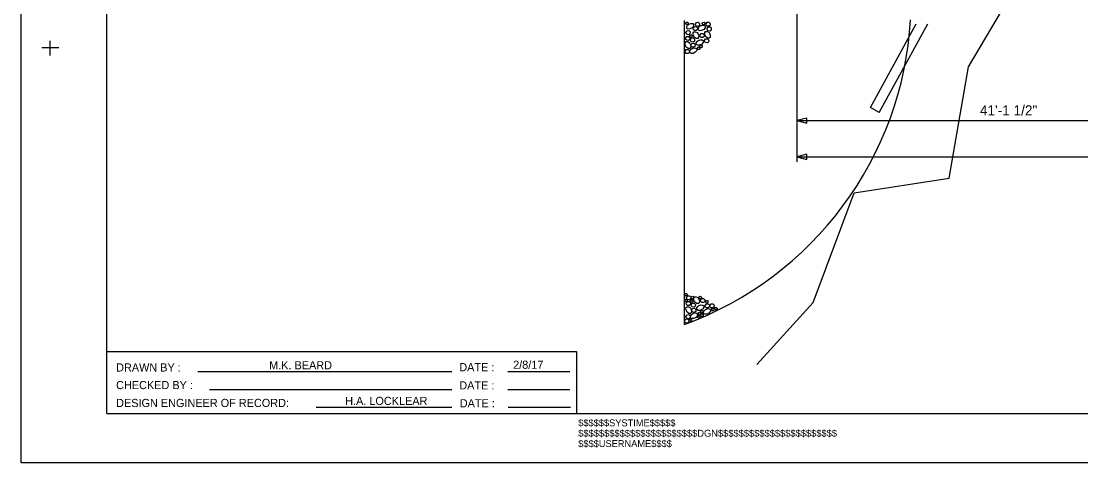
# Model space of a CAD drawing. Extents: x 985 to 1514, y -701 to -21.
# Drawn here: x 998.7 to 1102.9, y -220.9 to -177.5 of the extents above; entities that cross this region are included whole.
import ezdxf

# ---------------------------------------------------------------- set-up
doc = ezdxf.new("R2010")
doc.units = 0
for name, color, linetype in [('Auto Dimensioning', 7, 'Continuous'), ('Exist Hydro Stream or Body of Water', 7, 'Continuous'), ('Exist Structure Major Bridge Seam', 7, 'Continuous'), ('Miscellaneous Lines CELL', 7, 'Continuous'), ('Plan Sheet CELL', 7, 'Continuous'), ('Plot Label CELL', 7, 'Continuous'), ('Plot Shape CELL', 7, 'Continuous'), ('Sub End Bent Cap Lines CELL', 7, 'Continuous'), ('Subtitle Text', 7, 'Continuous'), ('Sup Concrete Girder Lines', 7, 'Continuous'), ('Text', 7, 'Continuous')]:
    doc.layers.add(name, color=color, linetype=linetype)

# ---------------------------------------------------------------- blocks, each defined once
blk = doc.blocks.new('AH')
at = {"layer": 'Sub End Bent Cap Lines CELL'}
blk.add_lwpolyline([(0, 0), (-1.25, 0.31), (-1.25, -0.31)], close=True, dxfattribs=at)

msp = doc.modelspace()

# ---------------------------------------------------------------- linework, layer by layer
at = {"layer": 'Auto Dimensioning'}
for p, q in [((1075, -159.49), (1075, -191.32)), ((1075, -187.25), (1116.12, -187.25)), ((1075, -190.82), (1157.23, -190.82))]:
    msp.add_line(p, q, dxfattribs=at)
at = {"layer": 'Exist Hydro Stream or Body of Water'}
for points in [[(1091.88, -181.98), (1095.35, -176.15), (1089.85, -166.68)], [(1071.09, -211.26), (1076.62, -205.16), (1080.66, -194.36), (1089.98, -192.93), (1091.88, -181.98)]]:
    msp.add_lwpolyline(points, dxfattribs=at)
at = {"layer": 'Exist Structure Major Bridge Seam'}
for p, q in [((1082.24, -185.97), (1086.76, -177.73)), ((1083.12, -186.45), (1087.9, -177.73)), ((1083.12, -186.45), (1082.24, -185.97))]:
    msp.add_line(p, q, dxfattribs=at)
at = {"layer": 'Miscellaneous Lines CELL'}
for points in [[(1064.08, -177.66), (1064.14, -177.56), (1064.25, -177.56), (1064.33, -177.63), (1064.32, -177.74), (1064.25, -177.8), (1064.14, -177.79), (1064.09, -177.74), (1064.08, -177.66)], [(1064.37, -177.78), (1064.58, -177.7), (1064.77, -177.71), (1064.86, -177.8), (1064.86, -177.96), (1064.72, -178.14), (1064.5, -178.24), (1064.3, -178.25), (1064.19, -178.17), (1064.18, -178), (1064.27, -177.86), (1064.38, -177.78)], [(1064.82, -178.18), (1064.93, -178.02), (1065.11, -178.01), (1065.24, -178.14), (1065.22, -178.32), (1065.11, -178.41), (1064.93, -178.4), (1064.85, -178.32), (1064.82, -178.18)], [(1065.03, -177.76), (1065.14, -177.6), (1065.32, -177.59), (1065.45, -177.72), (1065.43, -177.9), (1065.32, -177.99), (1065.14, -177.98), (1065.06, -177.9), (1065.03, -177.76)], [(1065.51, -177.95), (1065.72, -177.87), (1065.91, -177.88), (1066, -177.97), (1066, -178.13), (1065.86, -178.3), (1065.64, -178.41), (1065.44, -178.42), (1065.33, -178.33), (1065.32, -178.17), (1065.41, -178.03), (1065.51, -177.95)], [(1065.71, -177.7), (1065.78, -177.6), (1065.89, -177.59), (1065.96, -177.67), (1065.95, -177.78), (1065.88, -177.83), (1065.78, -177.83), (1065.73, -177.78), (1065.71, -177.7)], [(1066.08, -177.74), (1066.19, -177.58), (1066.37, -177.57), (1066.49, -177.7), (1066.48, -177.88), (1066.36, -177.97), (1066.19, -177.96), (1066.1, -177.88), (1066.08, -177.74)], [(1066.18, -178.21), (1066.3, -178.05), (1066.47, -178.04), (1066.6, -178.17), (1066.58, -178.35), (1066.47, -178.45), (1066.29, -178.43), (1066.21, -178.35), (1066.18, -178.21)], [(1064.07, -179.14), (1064.18, -178.98), (1064.36, -178.97), (1064.49, -179.1), (1064.47, -179.28), (1064.36, -179.37), (1064.18, -179.35), (1064.1, -179.27), (1064.07, -179.14)], [(1064.1, -178.58), (1064.21, -178.42), (1064.39, -178.41), (1064.52, -178.54), (1064.5, -178.72), (1064.39, -178.81), (1064.21, -178.8), (1064.13, -178.72), (1064.1, -178.58)], [(1064.49, -178.91), (1064.55, -178.81), (1064.66, -178.81), (1064.74, -178.88), (1064.72, -178.99), (1064.66, -179.05), (1064.55, -179.04), (1064.5, -178.99), (1064.49, -178.91)], [(1064.54, -179.29), (1064.66, -179.13), (1064.83, -179.12), (1064.96, -179.25), (1064.94, -179.43), (1064.83, -179.53), (1064.65, -179.51), (1064.57, -179.43), (1064.54, -179.29)], [(1065.28, -178.69), (1065.36, -178.9), (1065.34, -179.1), (1065.26, -179.19), (1065.1, -179.19), (1064.92, -179.05), (1064.82, -178.83), (1064.81, -178.63), (1064.89, -178.52), (1065.05, -178.51), (1065.2, -178.6), (1065.28, -178.7)], [(1065.48, -178.85), (1065.59, -178.69), (1065.77, -178.68), (1065.89, -178.81), (1065.88, -178.99), (1065.77, -179.09), (1065.59, -179.07), (1065.51, -178.99), (1065.48, -178.85)], [(1065.93, -179.37), (1066.04, -179.21), (1066.22, -179.2), (1066.34, -179.33), (1066.32, -179.51), (1066.21, -179.6), (1066.04, -179.59), (1065.95, -179.51), (1065.93, -179.37)], [(1066.42, -178.67), (1066.5, -178.88), (1066.48, -179.07), (1066.4, -179.16), (1066.24, -179.16), (1066.06, -179.02), (1065.95, -178.8), (1065.95, -178.6), (1066.03, -178.49), (1066.19, -178.48), (1066.34, -178.57), (1066.42, -178.68)], [(1064.5, -179.67), (1064.58, -179.88), (1064.56, -180.07), (1064.48, -180.16), (1064.32, -180.16), (1064.14, -180.02), (1064.04, -179.81), (1064.03, -179.61), (1064.11, -179.49), (1064.28, -179.48), (1064.42, -179.57), (1064.5, -179.68)], [(1064.03, -180.43), (1064.14, -180.28), (1064.32, -180.27), (1064.44, -180.39), (1064.42, -180.57), (1064.31, -180.67), (1064.14, -180.65), (1064.05, -180.57), (1064.03, -180.43)], [(1064.67, -180.19), (1064.88, -180.11), (1065.07, -180.12), (1065.17, -180.21), (1065.16, -180.37), (1065.02, -180.54), (1064.81, -180.65), (1064.61, -180.65), (1064.49, -180.57), (1064.48, -180.41), (1064.57, -180.27), (1064.68, -180.18)], [(1064.59, -179.82), (1064.71, -179.66), (1064.88, -179.65), (1065.01, -179.78), (1064.99, -179.96), (1064.88, -180.05), (1064.7, -180.04), (1064.62, -179.96), (1064.59, -179.82)], [(1065.3, -179.39), (1065.51, -179.3), (1065.7, -179.32), (1065.8, -179.41), (1065.79, -179.56), (1065.65, -179.74), (1065.44, -179.85), (1065.24, -179.85), (1065.12, -179.77), (1065.11, -179.61), (1065.21, -179.47), (1065.31, -179.38)], [(1065.22, -180.14), (1065.29, -180.05), (1065.4, -180.04), (1065.47, -180.12), (1065.46, -180.23), (1065.39, -180.28), (1065.29, -180.28), (1065.24, -180.23), (1065.22, -180.14)], [(1065.45, -179.95), (1065.52, -179.85), (1065.63, -179.85), (1065.7, -179.92), (1065.69, -180.03), (1065.63, -180.09), (1065.52, -180.08), (1065.47, -180.03), (1065.45, -179.95)], [(1063.98, -204.36), (1064.05, -204.26), (1064.15, -204.26), (1064.23, -204.33), (1064.22, -204.44), (1064.15, -204.5), (1064.05, -204.49), (1064, -204.44), (1063.98, -204.36)], [(1063.98, -204.92), (1064.05, -204.83), (1064.15, -204.82), (1064.23, -204.9), (1064.22, -205.01), (1064.15, -205.06), (1064.05, -205.05), (1064, -205.01), (1063.98, -204.92)], [(1064.14, -205.21), (1064.25, -205.05), (1064.43, -205.04), (1064.56, -205.17), (1064.54, -205.35), (1064.43, -205.44), (1064.25, -205.43), (1064.17, -205.35), (1064.14, -205.21)], [(1064.17, -204.66), (1064.28, -204.5), (1064.46, -204.49), (1064.59, -204.62), (1064.57, -204.8), (1064.46, -204.89), (1064.28, -204.88), (1064.2, -204.8), (1064.17, -204.66)], [(1064.56, -204.98), (1064.62, -204.89), (1064.73, -204.88), (1064.81, -204.96), (1064.79, -205.07), (1064.73, -205.12), (1064.62, -205.11), (1064.57, -205.07), (1064.56, -204.98)], [(1064.61, -204.64), (1064.68, -204.55), (1064.79, -204.54), (1064.86, -204.62), (1064.85, -204.73), (1064.79, -204.78), (1064.68, -204.78), (1064.63, -204.73), (1064.61, -204.64)], [(1064.61, -205.37), (1064.73, -205.21), (1064.9, -205.2), (1065.03, -205.33), (1065.01, -205.51), (1064.9, -205.6), (1064.72, -205.59), (1064.64, -205.51), (1064.61, -205.37)], [(1065.35, -204.77), (1065.43, -204.98), (1065.41, -205.17), (1065.33, -205.26), (1065.17, -205.26), (1064.99, -205.12), (1064.89, -204.91), (1064.88, -204.7), (1064.96, -204.59), (1065.12, -204.58), (1065.27, -204.67), (1065.35, -204.78)], [(1065.38, -204.64), (1065.44, -204.55), (1065.55, -204.54), (1065.63, -204.62), (1065.62, -204.73), (1065.55, -204.78), (1065.44, -204.78), (1065.39, -204.73), (1065.38, -204.64)], [(1065.55, -204.93), (1065.66, -204.77), (1065.84, -204.76), (1065.96, -204.89), (1065.95, -205.07), (1065.84, -205.16), (1065.66, -205.15), (1065.58, -205.07), (1065.55, -204.93)], [(1066, -205.45), (1066.11, -205.29), (1066.29, -205.28), (1066.41, -205.41), (1066.39, -205.59), (1066.28, -205.68), (1066.11, -205.67), (1066.02, -205.59), (1066, -205.45)], [(1066.03, -205.06), (1066.1, -204.96), (1066.21, -204.95), (1066.28, -205.03), (1066.27, -205.14), (1066.2, -205.2), (1066.1, -205.19), (1066.05, -205.14), (1066.03, -205.06)], [(1066.46, -205.45), (1066.57, -205.29), (1066.75, -205.28), (1066.87, -205.41), (1066.86, -205.59), (1066.74, -205.69), (1066.57, -205.67), (1066.48, -205.59), (1066.46, -205.45)], [(1064.57, -205.75), (1064.65, -205.96), (1064.63, -206.15), (1064.55, -206.24), (1064.39, -206.24), (1064.21, -206.1), (1064.11, -205.88), (1064.1, -205.68), (1064.18, -205.57), (1064.34, -205.56), (1064.49, -205.65), (1064.57, -205.75)], [(1064.1, -206.51), (1064.21, -206.35), (1064.39, -206.34), (1064.51, -206.47), (1064.49, -206.65), (1064.38, -206.74), (1064.21, -206.73), (1064.12, -206.65), (1064.1, -206.51)], [(1064.74, -206.26), (1064.95, -206.18), (1065.14, -206.2), (1065.24, -206.28), (1065.23, -206.44), (1065.09, -206.62), (1064.88, -206.73), (1064.68, -206.73), (1064.56, -206.65), (1064.55, -206.49), (1064.64, -206.34), (1064.75, -206.26)], [(1064.66, -205.89), (1064.78, -205.73), (1064.95, -205.72), (1065.08, -205.85), (1065.06, -206.03), (1064.95, -206.12), (1064.77, -206.11), (1064.69, -206.03), (1064.66, -205.89)], [(1065.37, -205.46), (1065.58, -205.38), (1065.77, -205.4), (1065.87, -205.48), (1065.86, -205.64), (1065.72, -205.82), (1065.51, -205.92), (1065.31, -205.93), (1065.19, -205.85), (1065.18, -205.69), (1065.27, -205.54), (1065.38, -205.46)], [(1065.29, -206.22), (1065.36, -206.12), (1065.47, -206.12), (1065.54, -206.19), (1065.53, -206.3), (1065.46, -206.36), (1065.36, -206.35), (1065.31, -206.3), (1065.29, -206.22)], [(1065.52, -206.02), (1065.59, -205.93), (1065.7, -205.92), (1065.77, -206), (1065.76, -206.11), (1065.69, -206.16), (1065.59, -206.16), (1065.54, -206.11), (1065.52, -206.02)], [(1065.55, -206.38), (1065.62, -206.28), (1065.73, -206.27), (1065.8, -206.35), (1065.79, -206.46), (1065.73, -206.51), (1065.62, -206.51), (1065.57, -206.46), (1065.55, -206.38)], [(1066.02, -205.84), (1066.23, -205.75), (1066.42, -205.77), (1066.52, -205.86), (1066.51, -206.01), (1066.37, -206.19), (1066.16, -206.3), (1065.96, -206.3), (1065.84, -206.22), (1065.83, -206.06), (1065.92, -205.92), (1066.03, -205.83)], [(1066.62, -205.84), (1066.69, -205.74), (1066.8, -205.74), (1066.87, -205.82), (1066.86, -205.92), (1066.79, -205.98), (1066.69, -205.97), (1066.64, -205.92), (1066.62, -205.84)], [(1066.92, -205.73), (1066.99, -205.63), (1067.09, -205.63), (1067.17, -205.7), (1067.16, -205.81), (1067.09, -205.87), (1066.98, -205.86), (1066.93, -205.81), (1066.92, -205.73)], [(1063.97, -206.94), (1064.08, -206.78), (1064.26, -206.77), (1064.38, -206.9), (1064.37, -207.08), (1064.25, -207.18), (1064.08, -207.16), (1063.99, -207.08), (1063.97, -206.94)], [(1064.42, -206.86), (1064.48, -206.76), (1064.59, -206.76), (1064.66, -206.84), (1064.65, -206.94), (1064.59, -207), (1064.48, -206.99), (1064.43, -206.94), (1064.42, -206.86)], [(1065.24, -206.56), (1065.31, -206.46), (1065.41, -206.46), (1065.49, -206.53), (1065.48, -206.64), (1065.41, -206.7), (1065.31, -206.69), (1065.26, -206.64), (1065.24, -206.56)]]:
    msp.add_lwpolyline(points, dxfattribs=at)
at = {"layer": 'Plan Sheet CELL'}
for p, q in [((1007.15, -216.07), (1007.15, -48.07)), ((1000.76, -180.07), (1002.44, -180.07)), ((1001.58, -180.86), (1001.58, -179.41)), ((1007.15, -209.97), (1053.35, -209.97)), ((1053.35, -209.97), (1053.35, -216.07)), ((1016.1, -211.95), (1041.08, -211.95)), ((1046.57, -211.95), (1052.69, -211.95)), ((1017.25, -213.71), (1041.08, -213.71)), ((1046.57, -213.71), (1052.69, -213.71)), ((1027.73, -215.46), (1041.08, -215.46)), ((1027.73, -215.46), (1041.08, -215.46)), ((1046.62, -215.46), (1052.74, -215.46)), ((1046.62, -215.46), (1052.74, -215.46)), ((1007.15, -216.07), (1263.16, -216.07)), ((998.72, -220.92), (998.72, -220.92))]:
    msp.add_line(p, q, dxfattribs=at)
at = {"layer": 'Plot Shape CELL'}
msp.add_lwpolyline([(998.72, -44.92), (1263.23, -44.92), (1263.23, -220.92), (998.72, -220.92)], close=True, dxfattribs=at)
at = {"layer": 'Sup Concrete Girder Lines'}
msp.add_line((1063.95, -207.32), (1063.95, -177.4), dxfattribs=at)
msp.add_arc((1052.22, -175.37), 34.03, 290.162, 356.6744, dxfattribs=at)

# ---------------------------------------------------------------- block references
at = {"layer": 'Auto Dimensioning', "xscale": 0.8, "yscale": 0.8000000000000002, "rotation": 180}
for p in [(1075, -187.25), (1075, -190.82)]:
    msp.add_blockref('AH', p, dxfattribs=at)

# ---------------------------------------------------------------- texts
at = {"layer": 'Plan Sheet CELL'}
for s, p in [('DRAWN BY :', (1008.06, -211.94)), ('DATE :', (1041.81, -211.91)), ('CHECKED BY :', (1008.06, -213.67)), ('DATE :', (1041.81, -213.7)), ('DESIGN ENGINEER OF RECORD:', (1008.06, -215.43)), ('DATE :', (1041.86, -215.46))]:
    msp.add_text(s, height=0.8, dxfattribs=at).set_placement(p)
at = {"layer": 'Plot Label CELL'}
for s, height, p in [('$$$$$$SYSTIME$$$$$', 0.6803, (1053.51, -217.33)), ('$$$$$$$$$$$$$$$$$$$$$$$DGN$$$$$$$$$$$$$$$$$$$$$$$', 0.6845, (1053.51, -218.35)), ('$$$$USERNAME$$$$', 0.6803, (1053.51, -219.37))]:
    msp.add_text(s, height=height, dxfattribs=at).set_placement(p)
at = {"layer": 'Subtitle Text'}
for s, p in [('M.K. BEARD', (1023.11, -211.72)), ('2/8/17', (1047.11, -211.67)), ('H.A. LOCKLEAR', (1030.59, -215.23))]:
    msp.add_text(s, height=0.8, dxfattribs=at).set_placement(p)
at = {"layer": 'Text'}
msp.add_text('41\'-1 1/2"', height=1, dxfattribs=at).set_placement((1093.02, -186.75))

doc.saveas('drawing.dxf')
